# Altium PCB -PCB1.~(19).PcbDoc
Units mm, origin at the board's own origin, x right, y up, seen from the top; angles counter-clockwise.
Board outline 80 x 60 mm, 2 copper layers (Top Layer, Bottom Layer); 29 components, 21 nets, 66 pads, 0 vias.
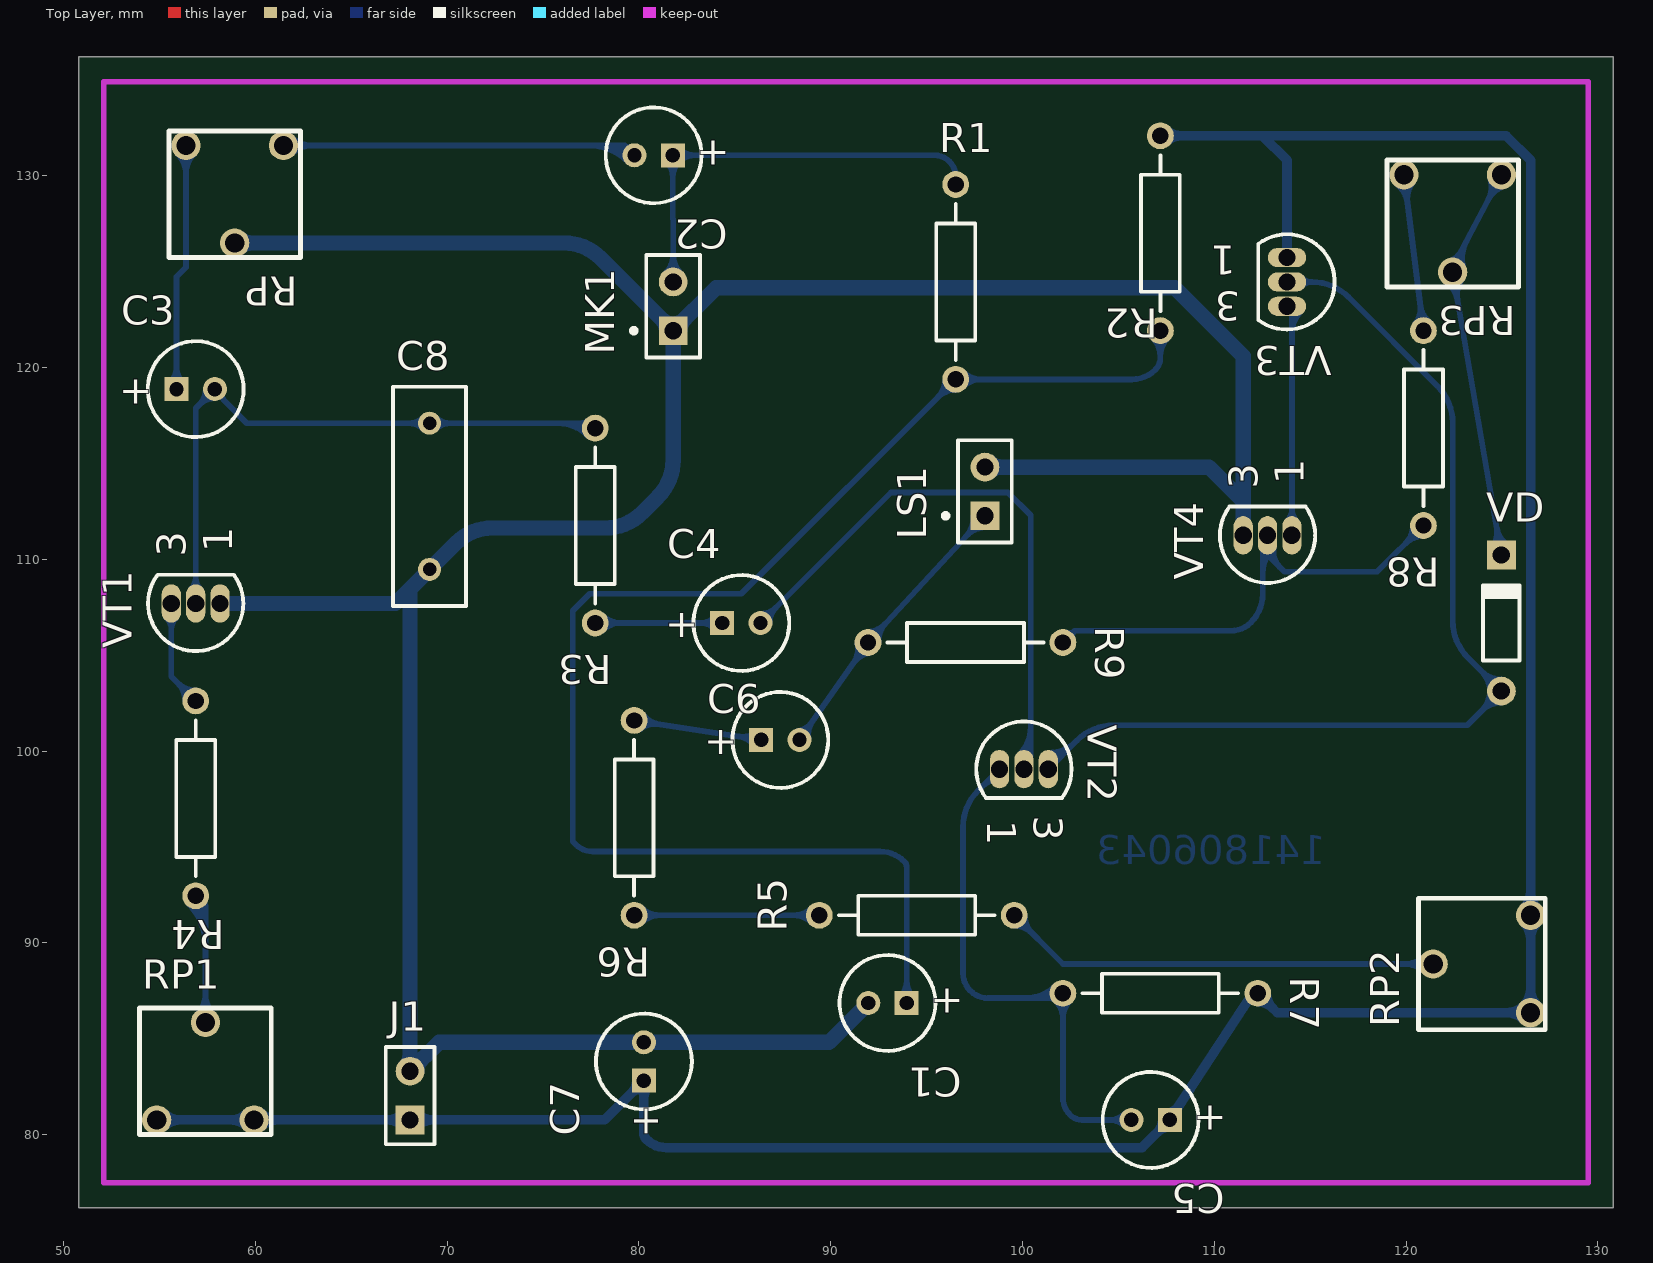
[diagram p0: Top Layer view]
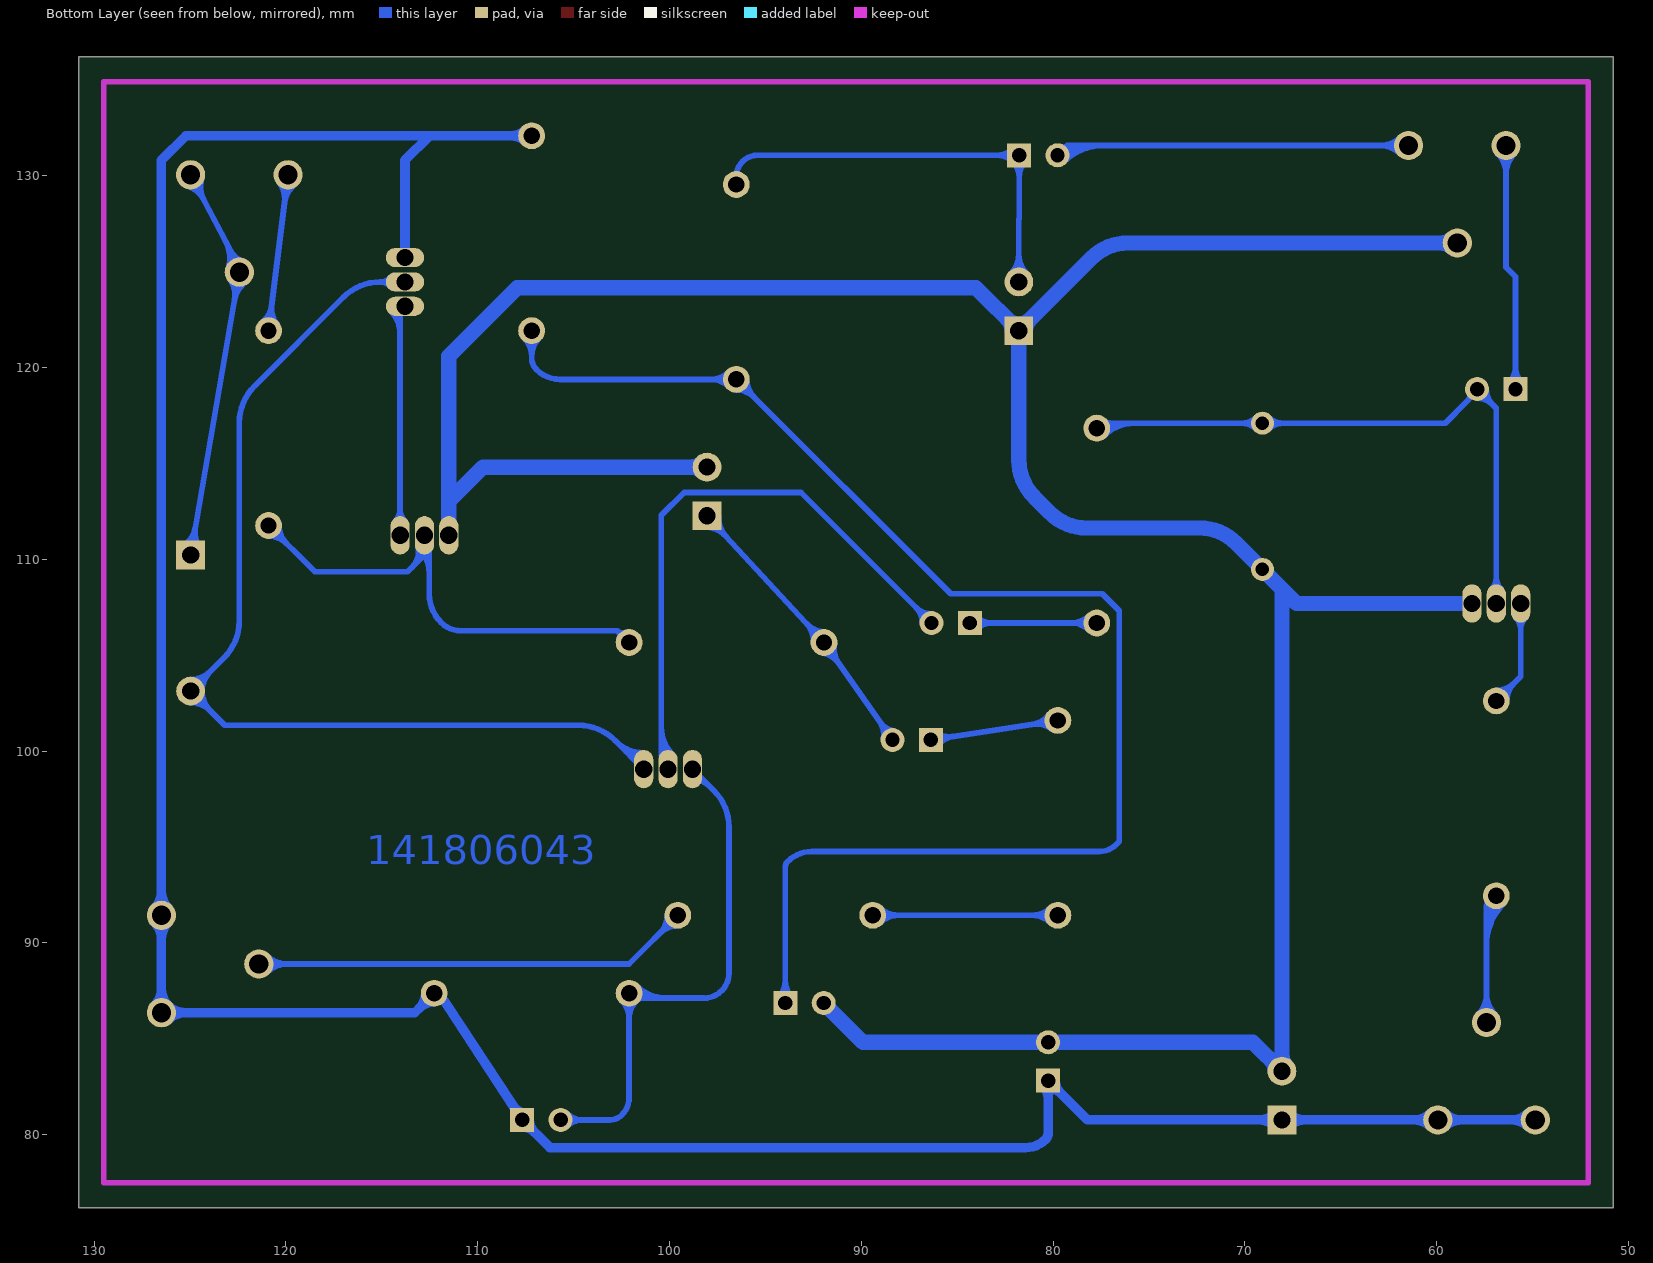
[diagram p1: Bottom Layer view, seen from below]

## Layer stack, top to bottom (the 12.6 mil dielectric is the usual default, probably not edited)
Top Layer: signal copper 0.0356
Dielectric: dielectric 0.32, FR-4, Dk 4.8
Bottom Layer: signal copper 0.0356

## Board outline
50.8,76.2 130.8,76.2 130.8,136.2 50.8,136.2

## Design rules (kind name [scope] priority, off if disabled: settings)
Clearance [All] p1: gap=0.2
ComponentClearance [All] p1: gap=0.254 collisioncheckmode=0
PolygonConnect [All] p1: connectstyle=Relief reliefconductorwidth=0.254 reliefentries=4 polygonreliefangle="90 Angle"
RoutingVias [All] p1: holewidth=0.8 width=1.8 viastyle="Through Hole" minholewidth=0.711 minwidth=1.27 maxholewidth=0.711 maxwidth=1.27
SolderMaskExpansion [All] p1: expansion=0.102
TestPointUsage [All] p1: valid=0 allowmultiple=FALSE
Testpoint [All] p1: side=15 testpointundercomponent=TRUE minsize=1.016 maxsize=2.54 preferedsize=1.524 minholesize=0 maxholesize=1.016 preferedholesize=0.813 testpointgrid=0.025 style=1023 order=1234567890
Width Width_2 [InNet('GND')] p1: maxlimit=0.8 minlimit=0.8 preferedwidth=0.8
Width Width_1 [InNet('VCC')] p2: maxlimit=0.5 minlimit=0.5 preferedwidth=0.5
Width [All] p3: maxlimit=0.3 minlimit=0.3 preferedwidth=0.3
17 further rules are at their usual default settings.

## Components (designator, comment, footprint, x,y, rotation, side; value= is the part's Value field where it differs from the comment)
C1 "Cap Pol1" CAPPR2-5x6.8 92.964,86.868 r180 top
C2 "Cap Pol1" CAPPR2-5x6.8 80.772,131.064 r180 top
C3 "Cap Pol1" CAPPR2-5x6.8 56.896,118.872 r0 top
C4 "Cap Pol1" CAPPR2-5x6.8 85.344,106.68 r0 top
C5 "Cap Pol1" CAPPR2-5x6.8 106.68,80.772 r180 top
C6 "Cap Pol1" CAPPR2-5x6.8 87.376,100.584 r0 top
C7 "Cap Pol1" CAPPR2-5x6.8 80.264,83.82 r90 top
C8 "Cap" RAD-0.3 69.088,113.284 r90 top
J1 "MHDR1X2" HDR1X2 68.072,80.772 r90 top
LS1 "Speaker" PIN2 98.044,112.268 r90 top
MK1 "Mic" PIN2 81.788,121.92 r90 top
R1 "Res2" AXIAL-0.4 96.52,124.46 r90 top
R2 "Res2" AXIAL-0.4 107.188,127 r270 top
R3 "Res2" AXIAL-0.4 77.724,111.76 r270 top
R4 "Res2" AXIAL-0.4 56.896,97.536 r270 top
R5 "Res2" AXIAL-0.4 94.488,91.44 r180 top
R6 "Res2" AXIAL-0.4 79.756,96.52 r270 top
R7 "47" AXIAL-0.4 107.188,87.376 r0 top
R8 "Res2" AXIAL-0.4 120.904,116.84 r270 top
R9 "Res2" AXIAL-0.4 97.028,105.664 r0 top
RP "RPot" RM065 58.928,129.032 r180 top
RP1 "RPot" RM065 57.404,83.312 r0 top
RP2 "RPot" RM065 123.952,88.9 r90 top
RP3 "100" RM065 122.428,127.508 r180 top
VD "4148" DIO7.1-3.9x1.9 124.968,106.68 r90 top
VT1 "9014" BCY-W3/E4 56.896,107.696 r90 top
VT2 "9015" BCY-W3/E4 100.076,99.06 r270 top
VT3 "8050" BCY-W3/E4 113.792,124.46 r180 top
VT4 "8550" BCY-W3/E4 112.776,111.252 r90 top

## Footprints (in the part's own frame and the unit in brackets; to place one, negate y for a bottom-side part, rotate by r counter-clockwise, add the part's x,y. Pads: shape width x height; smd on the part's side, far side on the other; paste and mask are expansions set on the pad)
AXIAL-0.4 [mm] "Resistor; 2 Leads"
  round 1.4 hole 0.85: 1(-5.08,0) 2(5.08,0)
  silkscreen extent -4.06,-1.02 4.06,1.02
BCY-W3/E4 [mm] "TO, Flat Index; 3 In-Line, Axial Leads; Body Dia. 4.7mm"
  oval 2x1 hole 0.9: 1(0,-1.27) 2(0,0) 3(0,1.27)
  silkscreen extent -2.48,-2.48 1.5,2.48
CAPPR2-5x6.8 [mm] "Capacitor, Electrolytic, Radial; Body 5 x 6.8 mm (Dia.xH typ); Pin Spacing 2 mm (typ)"
  rect 1.25x1.25 hole 0.75: 1(-1,0)
  round 1.25 hole 0.75: 2(1,0)
  silkscreen extent -2.5,-2.5 2.5,2.5
DIO7.1-3.9x1.9 [mm] "Diode, Axial; Body 3.8 x 1.9 mm (LxDia. max), Lead Dia. 0.53 mm (max)"
  round 1.5 hole 0.9: 1(-3.55,0)
  rect 1.5x1.5 hole 0.9: 2(3.55,0)
  silkscreen extent -1.95,-0.95 2.05,0.95
HDR1X2 [mm] "Connector; Header; 2 Position"
  rect 1.5x1.5 hole 0.9: 1(0,0)
  round 1.5 hole 0.9: 2(2.54,0)
  silkscreen extent -1.27,-1.27 3.81,1.27
PIN2 [mm] "Photosensitive Diode; 2 Leads"
  rect 1.5x1.5 hole 0.9: 1(0,0)
  round 1.5 hole 0.9: 2(2.54,0)
  silkscreen extent -1.4,-1.4 3.94,2.17
RAD-0.3 [mm] "Capacitor; 2 Leads"
  round 1.2 hole 0.7: 1(-3.81,0) 2(3.81,0)
  silkscreen extent -5.71,-1.91 5.71,1.91
RM065 [mil]
  round 60 hole 39.37: 1(100,-100) 2(0,100) 3(-100,-100)
  silkscreen extent -135,-130 135,130

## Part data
C1 C2 C3 C4 C5 C6 C7: "Polarized Capacitor (Radial)"
C8: "Capacitor"
J1: library part "Header 2", "Header, 2-Pin"
LS1: "Loudspeaker"
MK1: library part Mic2, "Microphone"
R1 R2 R3 R4 R5 R6 R8 R9: "Resistor"
R7: library part Res2, "Resistor"
RP RP1 RP2: "Potentiometer"
RP3: library part RPot, "Potentiometer"
VD: library part "Diode 1N4148", "High Conductance Fast Diode"
VT1: library part 2N3904, "NPN General Purpose Amplifier"
VT2 VT3 VT4: library part 2N3906, "PNP General Purpose Amplifier"

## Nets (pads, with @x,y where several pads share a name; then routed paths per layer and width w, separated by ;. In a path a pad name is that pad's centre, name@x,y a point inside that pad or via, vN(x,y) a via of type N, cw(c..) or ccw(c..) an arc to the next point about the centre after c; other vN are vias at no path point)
GND: C1.2 C7.2 C8.1 J1.2 LS1.2 MK1.1 RP.2 VT1.1 VT4.3 | length 173.9
  Bottom Layer w0.8: VT1.1 67.31,107.696 70.457,110.843 cw(c72.365,108.935) 72.365,111.633 78.257,111.633 ccw(c78.257,114.331) 80.165,112.423 80.998,113.256 ccw(c79.09,115.164) 81.788,115.164 MK1.1 ; RP.2 76.098,126.492 cw(c76.098,123.794) 78.006,125.702 MK1.1 ; RP.2@59.184,126.236 cw(c59.802,125.618) 59.802,126.492 cw(c59.802,127.366) RP.2@59.184,126.748 ; J1.2@67.825,83.559 ccw(c67.227,84.157) 68.072,84.157 ccw(c68.917,84.157) J1.2@68.319,83.559 ; J1.2@68.072,83.662 ccw(c68.072,84.507) 68.669,83.909 ccw(c69.267,83.312) J1.2@68.422,83.312 ; 68.072,108.458 J1.2 69.58,84.82 C7.2 89.916,84.82 C1.2 ; MK1.1@81.438,121.92 ccw(c80.593,121.92) 81.191,122.517 ccw(c81.788,123.115) 81.788,122.27 ccw(c81.788,123.115) 82.385,122.517 ccw(c82.983,121.92) MK1.1@82.138,121.92 ; MK1.1@81.541,121.673 cw(c80.943,121.075) 81.788,121.075 cw(c82.633,121.075) MK1.1@82.035,121.673 ; LS1.2 109.728,114.808 111.506,113.03 ; LS1.2@98.291,114.561 cw(c98.889,113.963) 98.889,114.808 cw(c98.889,115.653) LS1.2@98.291,115.055 ; VT4.3 111.506,120.599 107.95,124.155 84.023,124.155 MK1.1
NetC1_1: C1.1 R1.1 R2.2 | length 82.7
  Bottom Layer w0.3: C1.1@93.628,87.204 ccw(c92.817,88.015) 93.964,88.015 ccw(c95.111,88.015) C1.1@94.3,87.204 ; C1.1 93.964,93.966 ccw(c93.585,93.966) 93.853,94.234 ccw(c92.565,92.946) 92.565,94.767 77.597,94.767 cw(c77.597,96.021) 76.711,95.135 76.556,95.29 76.556,107.315 77.445,108.204 85.344,108.204 R1.1 105.708,119.38 ccw(c105.708,121.114) 106.934,119.888 ccw(c106.321,120.501) 107.188,120.501 R2.2 ; R1.1@95.97,119.38 cw(c94.642,119.38) 95.581,118.441 cw(c96.52,117.502) R1.1@96.52,118.83 ; R1.1@96.909,118.991 cw(c97.848,118.052) 97.848,119.38 cw(c97.848,120.708) R1.1@96.909,119.769 ; R2.2@106.799,121.531 cw(c105.86,120.592) 107.188,120.592 cw(c108.516,120.592) R2.2@107.577,121.531
NetC2_1: C2.1 MK1.2 R1.2 | length 28.3
  Bottom Layer w0.3: MK1.2@81.364,124.884 ccw(c80.339,125.909) 81.788,125.909 ccw(c83.237,125.909) MK1.2@82.212,124.884 ; C2.1@81.436,130.728 cw(c80.625,129.917) 81.772,129.917 cw(c82.919,129.917) 82.108,130.728 cw(c82.919,129.917) 82.919,131.064 cw(c82.919,132.211) C2.1@82.108,131.4 ; MK1.2 81.788,127.737 81.772,127.753 C2.1 95.402,131.064 cw(c95.402,129.946) 96.52,129.946 R1.2
NetC2_2: C2.2 RP.3 | length 26.6
  Bottom Layer w0.3: RP.3 79.264,131.572 ; RP.3@61.901,131.139 cw(c62.946,130.094) 62.946,131.572 cw(c62.946,133.05) RP.3@61.901,132.005 ; 77.399,131.572 cw(c77.399,128.691) C2.2@79.436,130.728 ; 78.123,131.572 cw(c78.123,129.415) C2.2@79.648,130.94 ; 78.847,131.572 cw(c78.847,130.139) C2.2@79.86,131.152 ; C2.2@79.331,131.242 ccw(c79.048,131.356) 79.264,131.572 ; C2.2@79.594,131.505 cw(c79.48,131.788) 79.264,131.572 ; C2.2 79.264,131.572
NetC3_1: C3.1 RP.1 | length 17
  Bottom Layer w0.3: C3.1@55.56,119.208 ccw(c54.749,120.019) 55.896,120.019 ccw(c57.043,120.019) C3.1@56.232,119.208 ; C3.1 55.896,124.73 56.388,125.222 RP.1 ; RP.1@55.955,131.139 cw(c54.91,130.094) 56.388,130.094 cw(c57.866,130.094) RP.1@56.821,131.139
NetC3_2: C3.2 C8.2 R3.1 VT1.2 | length 41.9
  Bottom Layer w0.3: VT1.2@56.649,108.443 ccw(c56.051,109.041) 56.896,109.041 ccw(c57.741,109.041) VT1.2@57.143,108.443 ; VT1.2 56.896,117.872 C3.2 ; C3.2@57.421,118.872 cw(c56.274,118.872) 57.085,118.061 cw(c57.896,117.25) C3.2@57.896,118.397 ; C3.2@58.166,118.872 ccw(c59.086,118.872) 58.435,118.222 59.563,117.094 77.111,117.094 cw(c77.111,116.227) R3.1 ; C8.2@68.77,116.776 ccw(c68.002,116.008) 68.002,117.094 ccw(c68.002,118.18) C8.2@68.77,117.412 ; C8.2@69.406,116.776 cw(c70.174,116.008) 70.174,117.094 cw(c70.174,118.18) C8.2@69.406,117.412 ; 75.783,117.094 cw(c75.783,114.899) R3.1@77.335,116.451 ; 76.507,117.094 cw(c76.507,115.623) R3.1@77.547,116.663 ; 77.009,117.094 ccw(c77.009,117.555) R3.1@77.335,117.229
NetC4_1: C4.1 R3.2 | length 10.5
  Bottom Layer w0.3: R3.2 C4.1 ; R3.2@78.113,106.291 cw(c79.052,105.352) 79.052,106.68 cw(c79.052,108.008) R3.2@78.113,107.069 ; C4.1@84.008,106.344 ccw(c83.197,105.533) 83.197,106.68 ccw(c83.197,107.827) C4.1@84.008,107.016
NetC4_2: C4.2 VT2.2 | length 35.2
  Bottom Layer w0.3: C4.2 93.151,113.487 99.238,113.487 100.432,112.293 100.432,99.918 cw(c99.218,99.918) VT2.2 ; C4.2@86.344,107.155 ccw(c86.344,108.302) 87.155,107.491 ccw(c87.966,106.68) C4.2@86.819,106.68 ; VT2.2@99.829,99.807 ccw(c98.373,101.263) 100.432,101.263 ; VT2.2@100.041,99.595 ccw(c99.097,100.539) 100.432,100.539
NetC5_2: C5.2 R7.1 VT2.1 | length 35.1
  Bottom Layer w0.3: 97.917,98.171 cw(c98.74,97.347) VT2.1@98.803,98.51 ; VT2.1 97.691,97.945 ccw(c99.599,96.037) 96.901,96.037 96.901,88.423 ccw(c98.202,88.423) 97.282,87.503 ccw(c98.202,88.423) 98.202,87.122 101.495,87.122 ccw(c101.495,87.989) R7.1 102.108,81.946 ccw(c103.409,81.946) 102.489,81.026 ccw(c103.102,81.639) 103.102,80.772 C5.2 ; 100.167,87.122 ccw(c100.167,89.317) R7.1@101.719,87.765 ; 100.891,87.122 ccw(c100.891,88.593) R7.1@101.931,87.553 ; 101.393,87.122 cw(c101.393,86.661) 101.719,86.987 cw(c100.78,86.048) 102.108,86.048 cw(c103.436,86.048) R7.1@102.497,86.987 ; C5.2@105.344,80.436 ccw(c104.533,79.625) 104.533,80.772 ccw(c104.533,81.919) C5.2@105.344,81.108
NetC6_1: C6.1 R6.1 | length 10.6
  Bottom Layer w0.3: R6.1 C6.1 ; R6.1@80.081,101.157 cw(c80.867,100.086) 81.068,101.399 cw(c81.27,102.711) R6.1@80.199,101.925 ; C6.1@85.993,100.303 ccw(c85.069,99.624) 85.243,100.758 ccw(c85.416,101.891) C6.1@86.095,100.967
NetC6_2: C6.2 LS1.1 R9.1 | length 23.4
  Bottom Layer w0.3: C6.2@88.294,101.052 ccw(c88.098,102.182) 89.036,101.522 ccw(c89.974,100.862) C6.2@88.844,100.666 ; C6.2 R9.1 LS1.1 ; R9.1@91.406,105.57 cw(c90.098,105.342) 91.184,104.578 cw(c92.27,103.814) R9.1@92.042,105.122 ; R9.1@91.926,106.214 ccw(c91.873,107.54) 92.849,106.64 ccw(c93.824,105.739) R9.1@92.498,105.686 ; LS1.1@97.444,112.244 cw(c95.997,112.186) 97.061,111.204 cw(c98.126,110.221) LS1.1@98.068,111.668
NetR4_1: R4.1 VT1.3 | length 9
  Bottom Layer w0.3: VT1.3@55.379,106.949 cw(c54.781,106.351) 55.626,106.351 cw(c56.471,106.351) VT1.3@55.873,106.949 ; VT1.3 55.626,103.886 R4.1 ; R4.1@56.346,102.616 ccw(c55.018,102.616) 55.957,103.555 ccw(c56.896,104.494) R4.1@56.896,103.166
NetR4_2: R4.2 RP1.2 | length 15.2
  Bottom Layer w0.3: R4.2@56.507,92.067 cw(c54.342,89.902) 57.404,89.902 ; R4.2@56.719,92.279 cw(c55.066,90.626) 57.404,90.626 ; R4.2 57.404,91.948 ; R4.2@56.931,92.491 cw(c55.79,91.35) 57.404,91.35 ; RP1.2@56.971,86.285 ccw(c55.926,87.33) 57.404,87.33 ccw(c58.882,87.33) RP1.2@57.837,86.285 ; R4.2@57.17,91.979 cw(c57.267,91.811) 57.404,91.948 ; R4.2@57.373,92.182 ccw(c57.541,92.085) 57.404,91.948 ; RP1.2 57.404,91.948
NetR5_1: R5.1 RP2.2 | length 27.3
  Bottom Layer w0.3: R5.1@99.568,90.89 cw(c99.568,89.562) 100.507,90.501 cw(c101.446,91.44) R5.1@100.118,91.44 ; R5.1 102.108,88.9 RP2.2 ; RP2.2@120.979,88.467 ccw(c119.934,87.422) 119.934,88.9 ccw(c119.934,90.378) RP2.2@120.979,89.333
NetR5_2: R5.2 R6.2 | length 14.1
  Bottom Layer w0.3: R6.2 R5.2@89.662,91.44 ; R6.2@80.145,91.051 cw(c81.084,90.112) 81.084,91.44 cw(c81.084,92.768) R6.2@80.145,91.829 ; R5.2@89.019,91.051 ccw(c88.08,90.112) 88.08,91.44 ccw(c88.08,92.768) R5.2@89.019,91.829
NetR8_1: R8.1 RP3.1 | length 12.6
  Bottom Layer w0.3: RP3.1@119.512,129.565 cw(c118.605,128.399) 120.071,128.582 cw(c121.537,128.765) RP3.1@120.371,129.672 ; RP3.1 R8.1 ; R8.1@120.47,122.258 ccw(c119.422,123.073) 120.739,123.238 ccw(c122.057,123.402) R8.1@121.242,122.354
NetR8_2: R8.2 R9.2 VT4.2 | length 33.3
  Bottom Layer w0.3: R9.2 102.713,106.269 ; R9.2@102.301,106.179 ccw(c102.437,106.544) 102.713,106.269 ; R9.2@102.623,105.857 cw(c102.988,105.993) 102.713,106.269 ; 112.522,109.294 cw(c114.234,109.294) VT4.2@113.023,110.505 ; 112.522,110.018 cw(c113.51,110.018) VT4.2@112.811,110.717 ; VT4.2@112.522,111.125 112.522,108.179 cw(c110.437,108.179) 111.911,106.704 cw(c110.865,107.751) 110.865,106.271 102.718,106.271 ccw(c102.718,106.264) 102.713,106.269 ; VT4.2 112.776,110.236 ; VT4.2@112.824,110.74 ccw(c113.599,110.543) 113.034,109.978 ; VT4.2@113.115,110.666 ccw(c114.194,110.392) 113.407,109.605 ; R8.2@120.354,111.76 cw(c119.026,111.76) 119.965,110.821 cw(c120.904,109.882) R8.2@120.904,111.21 ; R8.2 118.491,109.347 113.665,109.347 112.776,110.236 ; 112.776,110.236 cw(c112.981,110.236) 112.905,110.427 ccw(c112.981,110.236) 112.776,110.236 ; 112.776,110.236 ccw(c112.571,110.236) 112.647,110.427 cw(c112.571,110.236) 112.776,110.236
NetRP3_2: RP3.2 RP3.3 VD.2 | length 30.6
  Bottom Layer w0.3: RP3.2@122.075,124.468 cw(c121.223,123.261) 122.679,123.512 cw(c124.135,123.763) RP3.2@122.928,124.615 ; RP3.2@122.247,125.553 ccw(c121.928,126.578) 122.878,126.078 ; RP3.2 VD.2 ; RP3.2@122.428,125.222 RP3.3 ; RP3.2@122.726,125.06 cw(c123.831,125.403) 122.807,125.942 ; RP3.2@123.013,125.149 cw(c124.809,125.707) 123.144,126.583 ; RP3.3@124.384,129.867 cw(c122.972,129.429) 124.28,128.741 cw(c125.587,128.052) RP3.3@125.149,129.464 ; VD.2@124.478,110.576 ccw(c123.295,111.411) 124.722,111.657 ccw(c126.149,111.904) VD.2@125.314,110.72
NetVD_1: VD.1 VT2.3 VT3.2 | length 60.6
  Bottom Layer w0.3: VT2.3 102.842,100.556 cw(c104.75,98.648) 104.75,101.346 123.184,101.346 VD.1 123.218,104.88 cw(c125.126,106.788) 122.428,106.788 122.428,117.119 ccw(c119.73,117.119) 121.638,119.027 116.995,123.67 ccw(c115.087,121.762) 115.898,124.335 ccw(c115.087,121.762) 115.087,124.46 ; VT2.3@101.346,99.61 ccw(c101.346,100.938) 102.285,99.999 ; VT2.3@101.346,99.91 ccw(c101.346,101.962) 102.797,100.511 ; VT3.2 115.087,124.46 ; VT3.2@114.55,124.224 cw(c115.087,123.731) 115.087,124.46 ; VT3.2@114.55,124.696 ccw(c115.087,125.189) 115.087,124.46 ; VD.1@124.968,102.53 ccw(c124.968,101.081) 123.944,102.106 ccw(c122.919,103.13) 124.368,103.13 ccw(c122.919,103.13) 123.944,104.154 ccw(c124.968,105.179) VD.1@124.968,103.73
NetVT3_3: VT3.3 VT4.1 | length 15.6
  Bottom Layer w0.3: VT3.3 114.046,123.19 VT4.1 ; VT4.1@113.799,111.999 ccw(c113.201,112.597) 114.046,112.597 ccw(c114.891,112.597) VT4.1@114.293,111.999 ; 114.046,121.751 cw(c115.731,121.751) VT3.3@114.539,122.943 ; 114.046,122.475 cw(c115.007,122.475) VT3.3@114.327,123.155
VCC: C5.1 C7.1 J1.1 R2.1 R7.2 RP1.1 RP1.3 RP2.1 RP2.3 VT3.1 | length 178.7
  Bottom Layer w0.5: RP1.3 RP1.1 J1.1 78.216,80.772 C7.1 80.264,80.063 ccw(c80.698,80.063) 80.391,79.756 ccw(c81.433,80.798) 81.433,79.324 106.232,79.324 C5.1 111.529,86.637 R7.2@112.014,87.376 ; RP1.3@55.226,80.41 cw(c56.1,79.536) 56.1,80.772 cw(c56.1,82.008) RP1.3@55.226,81.134 ; RP1.1@59.582,80.41 ccw(c58.708,79.536) 58.708,80.772 ccw(c58.708,82.008) RP1.1@59.582,81.134 ; RP1.1@60.306,80.41 cw(c61.18,79.536) 61.18,80.772 cw(c61.18,82.008) RP1.1@60.306,81.134 ; J1.1@67.718,80.418 ccw(c66.865,79.565) 66.865,80.772 ccw(c66.865,81.979) J1.1@67.718,81.126 ; J1.1@68.426,80.418 cw(c69.279,79.565) 69.279,80.772 cw(c69.279,81.979) J1.1@68.426,81.126 ; C7.1@79.889,82.82 cw(c78.984,82.82) 79.624,82.18 cw(c80.264,81.54) C7.1@80.264,82.445 ; C7.1@79.999,82.555 cw(c79.359,81.915) 80.264,81.915 cw(c81.169,81.915) C7.1@80.529,82.555 ; R2.1 112.522,132.08 ; C5.1@107.305,80.772 cw(c106.4,80.772) 107.04,80.132 cw(c107.68,79.492) C5.1@107.68,80.397 ; R2.1@107.506,131.762 cw(c108.274,130.994) 108.274,132.08 cw(c108.274,133.166) R2.1@107.506,132.398 ; C5.1@107.604,81.139 ccw(c107.42,82.026) 108.177,81.529 ccw(c108.934,81.032) C5.1@108.047,80.848 ; R7.2@112.141,87.249 R7.2 113.284,86.36 RP2.3 RP2.1 126.492,130.81 125.222,132.08 112.522,132.08 ; R7.2@112.268,86.926 cw(c112.268,85.84) 113.036,86.608 cw(c113.804,87.376) R7.2@112.718,87.376 ; VT3.1@113.615,125.907 ccw(c113.188,126.334) 113.792,126.334 ccw(c114.396,126.334) VT3.1@113.969,125.907 ; VT3.1 113.792,130.81 112.522,132.08 ; RP2.3@126.13,85.998 ccw(c125.256,85.124) 125.256,86.36 ccw(c125.256,87.596) 126.13,86.722 ccw(c125.256,87.596) 126.492,87.596 ccw(c127.728,87.596) RP2.3@126.854,86.722 ; RP2.1@126.13,91.078 cw(c125.256,90.204) 126.492,90.204 cw(c127.728,90.204) RP2.1@126.854,91.078 ; RP2.1@126.13,91.802 ccw(c125.256,92.676) 126.492,92.676 ccw(c127.728,92.676) RP2.1@126.854,91.802

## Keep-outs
Keep-Out Layer:
  lines w0.3: 52.1,77.5 52.1,134.9 129.5,134.9 129.5,77.5 52.1,77.5

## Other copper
Bottom Layer:
  text "141806043" at 115.824,94.107 h1.52

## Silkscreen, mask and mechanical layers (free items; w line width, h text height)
Drill Drawing:
  text ".LEGEND" at 135.88,81.28 h1.52
  text "Drill Drawing." at 135.88,78.74 h1.52

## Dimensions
52.1,77.5 to 52.1,134.9 on Mechanical 1
52.1,77.5 to 129.5,77.5 on Mechanical 1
